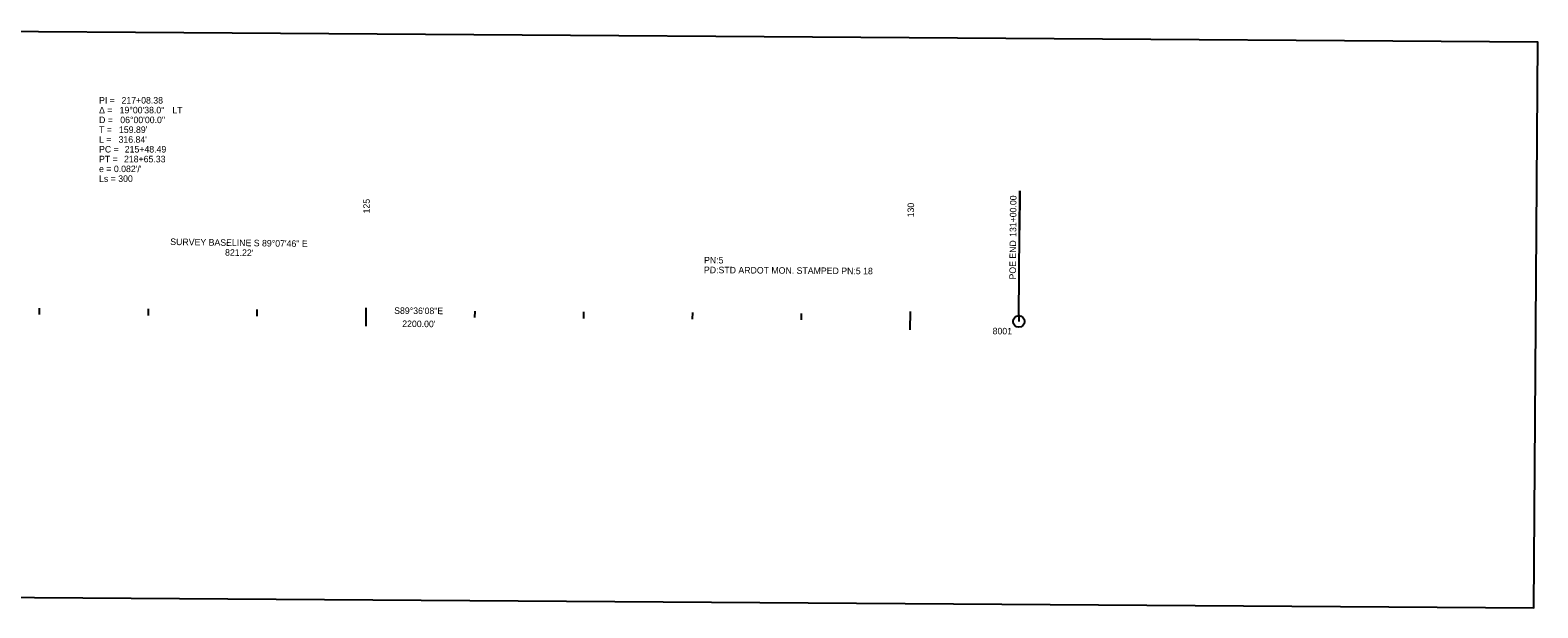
# Model space of a CAD drawing. Extents: x 1801895 to 1805049, y 572742 to 575010.
# Drawn here: x 1803664 to 1805049, y 573541 to 574073 of the extents above; entities that cross this region are included whole.
import ezdxf

# ---------------------------------------------------------------- set-up
doc = ezdxf.new("R2010")
doc.units = 0
for name, color, linetype in [('_CIVIL_CONSTRUCTION', 7, 'Continuous'), ('DSN_DRFT_Named-Boundary', 7, 'Continuous'), ('DSN_RDWY_Alignment Annotation', 7, 'Continuous'), ('DSN_ROW_Point-Annotation', 7, 'Continuous'), ('S_BASELINE_ANNOT', 7, 'Continuous')]:
    doc.layers.add(name, color=color, linetype=linetype)

msp = doc.modelspace()

# ---------------------------------------------------------------- linework, layer by layer
at = {"layer": 'DSN_DRFT_Named-Boundary'}
msp.add_lwpolyline([(1803449, 574072.5), (1803445.3, 573552.5), (1805045.3, 573541.4), (1805048.9, 574061.4)], close=True, dxfattribs=at)
at = {"layer": 'DSN_RDWY_Alignment Annotation'}
for p, q in [((1804572.2, 573810), (1804573, 573924.7)), ((1804573, 573924.7), (1804572.7, 573888.7)), ((1803672.2, 573817), (1803672.1, 573811)), ((1803772.2, 573816.3), (1803772.1, 573810.3)), ((1803872.2, 573815.6), (1803872.1, 573809.6)), ((1803972.2, 573817.3), (1803972.1, 573800.5)), ((1804072.2, 573814.2), (1804072.1, 573808.2)), ((1804172.2, 573813.5), (1804172.1, 573807.5)), ((1804272.2, 573812.8), (1804272.1, 573806.8)), ((1804372.2, 573812.1), (1804372.1, 573806.1)), ((1804472.2, 573813.8), (1804472.1, 573797)), ((1804572.2, 573810.7), (1804572.1, 573804.7)), ((1804572.1, 573804.7), (1804572.1, 573804.7))]:
    msp.add_line(p, q, dxfattribs=at)
msp.add_circle((1804572.1, 573804.7), 5.34, dxfattribs=at)

# ---------------------------------------------------------------- texts
at = {"layer": '_CIVIL_CONSTRUCTION'}
for s, p in [('SURVEY BASELINE S 89°07\'46" E', (1803792.5, 573875)), ("821.22'", (1803842.8, 573865.2))]:
    msp.add_text(s, height=6, rotation=359.1294, dxfattribs=at).set_placement(p)
at = {"layer": 'DSN_RDWY_Alignment Annotation'}
for s, p in [('PI = ', (1803727.1, 574005)), ('217+08.38', (1803747.7, 574005)), ('Δ = ', (1803727.1, 573996)), ('19°00\'38.0"', (1803746, 573996)), (' LT', (1803792.2, 573996)), ('T = ', (1803727.1, 573978)), ('D = ', (1803727.1, 573987)), ("159.89'", (1803745.4, 573978)), ('06°00\'00.0"', (1803746.6, 573987)), ('L = ', (1803727.1, 573969)), ("316.84'", (1803745, 573969)), ('PC = ', (1803727.1, 573960)), ('PT = ', (1803727.1, 573951)), ('218+65.33', (1803750, 573951)), ('215+48.49', (1803750.7, 573960)), ("e = 0.082'/'", (1803727.1, 573942)), ('Ls = 300', (1803727.1, 573933))]:
    msp.add_text(s, height=6, dxfattribs=at).set_placement(p)
for s, rotation, p in [('125', 89.6021, (1803975.8, 573904)), ('130', 89.6021, (1804475.8, 573900.4)), ('131+00.00', 89.6021, (1804569.7, 573882.4)), ('END', 89.6021, (1804569.5, 573862.4)), ('POE ', 89.6021, (1804569.4, 573843.3)), ('S89°36\'08"E', 359.6021, (1803998.2, 573811.7)), ('8001', 359.6021, (1804548, 573792.9))]:
    msp.add_text(s, height=6, rotation=rotation, dxfattribs=at).set_placement(p)
at = {"layer": 'DSN_ROW_Point-Annotation'}
msp.add_text("2200.00'", height=6, rotation=359.6021, dxfattribs=at).set_placement((1804005.6, 573799.6))
at = {"layer": 'S_BASELINE_ANNOT'}
for s, p in [('PN:5', (1804282.9, 573858.1)), ('PD:STD ARDOT MON. STAMPED PN:5 18', (1804282.8, 573849.1))]:
    msp.add_text(s, height=6, rotation=359.6021, dxfattribs=at).set_placement(p)

doc.saveas('drawing.dxf')
